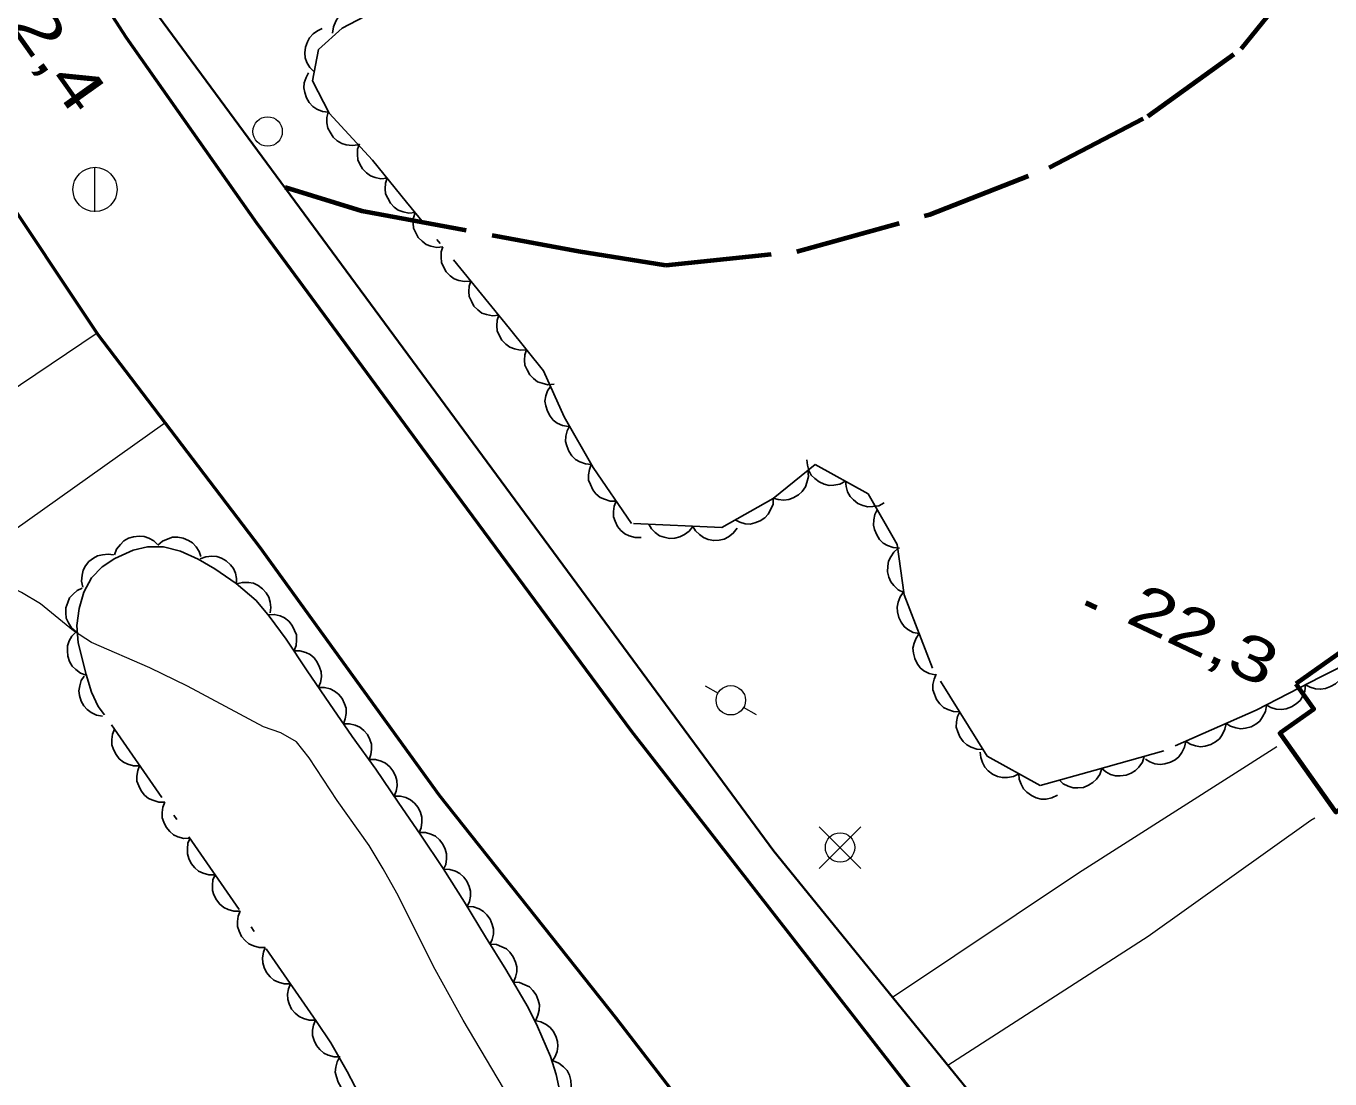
# Model space of a CAD drawing. Extents: x 356765 to 358572, y 5103174 to 5104650.
# Drawn here: x 357029.21 to 357073.46, y 5104052.73 to 5104088.48 of the extents above; entities that cross this region are included whole.
import ezdxf

# ---------------------------------------------------------------- set-up
doc = ezdxf.new("R2010")
doc.units = 0
doc.header["$LTSCALE"] = 0.6
doc.linetypes.add('DOT_DASHED', pattern=[7.7, 5, -1.2, 0.3, -1.2])
doc.linetypes.add('LONG_DASHED', pattern=[7.5, 6, -1.5])
for name, color, linetype, lineweight in [('19', 7, 'Continuous', 13), ('2', 7, 'Continuous', 13), ('21', 7, 'Continuous', 53), ('22', 7, 'Continuous', 35), ('3', 7, 'Continuous', 140), ('31', 7, 'Continuous', 70), ('36', 7, 'Continuous', 13), ('44', 7, 'Continuous', 25)]:
    doc.layers.add(name, color=color, linetype=linetype, lineweight=lineweight)

msp = doc.modelspace()

# ---------------------------------------------------------------- linework, layer by layer
at = {"layer": '19'}
msp.add_line((357022.12, 5104066.62), (357033.92, 5104075.01), dxfattribs=at)
for points in [[(357031.62, 5104078.05), (357020.19, 5104070.36), (357020.33, 5104069.93)], [(357071.66, 5104064.01), (357064.93, 5104059.72), (357058.62, 5104055.5)], [(357060.49, 5104053.2), (357067.3, 5104057.58), (357072.82, 5104061.51), (357072.95, 5104061.59)]]:
    msp.add_lwpolyline(points, dxfattribs=at)
at = {"layer": '2'}
msp.add_lwpolyline([(357047.18, 5104049.44), (357044.04, 5104054.73), (357043.09, 5104056.45), (357041.79, 5104059.04), (357041.33, 5104059.86), (357040.85, 5104060.65), (357039.76, 5104062.18), (357038.82, 5104063.63), (357038.38, 5104064.18), (357037.85, 5104064.48), (357037.26, 5104064.69), (357034.69, 5104066.07), (357033.41, 5104066.69), (357031.43, 5104067.55), (357030.82, 5104067.94), (357029.69, 5104068.86), (357029.05, 5104069.25), (357027.71, 5104069.88), (357027.14, 5104070.19)], dxfattribs=at)
at = {"layer": '21'}
for points in [[(357013.37, 5104117.93), (357021.55, 5104104.79), (357028.8, 5104093.99), (357032.6, 5104088.09), (357037.03, 5104081.8), (357042.63, 5104074.18), (357049.74, 5104064.55), (357059.41, 5104052.15)], [(357010.13, 5104111.16), (357012.95, 5104106.67), (357018.36, 5104098.18), (357024.48, 5104088.75), (357031.64, 5104078.01), (357037.13, 5104070.8), (357043.23, 5104062.36), (357049.22, 5104054.8), (357051.56, 5104051.78)]]:
    msp.add_lwpolyline(points, dxfattribs=at)
at = {"layer": '22'}
msp.add_lwpolyline([(357221.36, 5103864.57), (357203.17, 5103886.01), (357184.34, 5103907.9), (357170.96, 5103923.59), (357161.12, 5103935.05), (357158.11, 5103938.34), (357149.98, 5103947.63), (357129.46, 5103972.34), (357111.79, 5103992.65), (357092.35, 5104015.36), (357072.16, 5104038.84), (357054.59, 5104060.46), (357032.27, 5104090.76), (357019.29, 5104110.68), (357013.99, 5104119.24)], dxfattribs=at)
at = {"layer": '22', "linetype": 'LONG_DASHED', "lineweight": 70}
msp.add_lwpolyline([(357038, 5104083.01), (357040.6, 5104082.2), (357047.96, 5104080.84), (357050.92, 5104080.36), (357055.37, 5104080.82), (357059.88, 5104082.08), (357063.94, 5104083.67), (357067.28, 5104085.42), (357070.45, 5104087.71), (357072.96, 5104090.8)], dxfattribs=at)
at = {"layer": '3'}
msp.add_line((357065.18, 5104068.9), (357065.54, 5104068.73), dxfattribs=at)
at = {"layer": '31'}
msp.add_lwpolyline([(357072.31, 5104066.15), (357072.92, 5104065.29), (357071.76, 5104064.47), (357073.66, 5104061.79), (357074.66, 5104062.49), (357076.12, 5104060.42), (357081.38, 5104064.14), (357077.41, 5104069.75), (357072.31, 5104066.15)], close=True, dxfattribs=at)
at = {"layer": '36'}
for p, q in [((357031.54, 5104082.17), (357031.54, 5104083.67)), ((357052.26, 5104066.08), (357052.7, 5104065.83)), ((357054, 5104065.09), (357053.56, 5104065.34)), ((357057.54, 5104059.88), (357056.13, 5104061.29)), ((357056.13, 5104059.88), (357057.54, 5104061.29))]:
    msp.add_line(p, q, dxfattribs=at)
for centre, radius in [((357037.4038, 5104084.8971), 0.5), ((357031.5447, 5104082.9312), 0.75), ((357053.1261, 5104065.5865), 0.5), ((357056.8368, 5104060.5874), 0.5)]:
    msp.add_circle(centre, radius, dxfattribs=at)
at = {"layer": '44', "linetype": 'DOT_DASHED'}
for points in [[(357075.36, 5104067.5), (357073.16, 5104066.38), (357070.96, 5104065.25), (357067.83, 5104063.87), (357065.5, 5104063.21), (357063.63, 5104062.69), (357061.83, 5104063.69), (357059.97, 5104066.68), (357059.01, 5104069.17), (357058.78, 5104070.87), (357057.79, 5104072.59), (357055.99, 5104073.59), (357054.56, 5104072.44), (357052.82, 5104071.45), (357049.76, 5104071.59), (357048.46, 5104073.49), (357047.47, 5104075.21), (357046.77, 5104076.77), (357045.61, 5104078.21), (357042.12, 5104082.5), (357040.96, 5104083.93), (357039.49, 5104085.52), (357038.93, 5104086.62), (357039.13, 5104087.68), (357039.93, 5104088.41), (357044.09, 5104090.58)], [(357040.63, 5104051.99), (357040.11, 5104052.98), (357039.55, 5104053.95), (357039.06, 5104054.68), (357031.87, 5104065.09), (357031.65, 5104065.38), (357031.43, 5104065.86), (357031.24, 5104066.46), (357030.97, 5104067.54), (357030.93, 5104068.12), (357031.01, 5104068.7), (357031.17, 5104069.26), (357031.43, 5104069.74), (357031.79, 5104070.12), (357032.22, 5104070.4), (357032.84, 5104070.68), (357033.33, 5104070.8), (357033.87, 5104070.8), (357034.45, 5104070.65), (357035.05, 5104070.38), (357035.61, 5104070.05), (357036.34, 5104069.55), (357037.01, 5104068.97), (357037.46, 5104068.44), (357038.03, 5104067.66), (357038.75, 5104066.59), (357039.5, 5104065.48), (357040.28, 5104064.36), (357041.08, 5104063.25), (357041.84, 5104062.13), (357042.61, 5104061.01), (357043.36, 5104059.88), (357044.09, 5104058.73), (357044.8, 5104057.55), (357045.49, 5104056.44), (357046.25, 5104055.16), (357046.56, 5104054.51), (357047.01, 5104053.49), (357047.2, 5104052.88), (357047.36, 5104052.15)]]:
    msp.add_lwpolyline(points, dxfattribs=at)
at = {"layer": '44'}
for points in [[(357039.61, 5104088.24), (357039.64, 5104088.45), (357039.72, 5104088.64), (357039.8, 5104088.78), (357039.93, 5104088.9), (357040.09, 5104089), (357040.27, 5104089.06), (357040.43, 5104089.09), (357040.61, 5104089.07), (357040.78, 5104089.02), (357040.94, 5104088.94)], [(357038.99, 5104086.92), (357038.84, 5104087.07), (357038.74, 5104087.24), (357038.68, 5104087.4), (357038.67, 5104087.57), (357038.69, 5104087.76), (357038.76, 5104087.94), (357038.83, 5104088.08), (357038.95, 5104088.21), (357039.1, 5104088.32), (357039.26, 5104088.39)], [(357039.47, 5104085.55), (357039.27, 5104085.58), (357039.08, 5104085.66), (357038.94, 5104085.75), (357038.82, 5104085.88), (357038.72, 5104086.04), (357038.67, 5104086.22), (357038.63, 5104086.38), (357038.65, 5104086.55), (357038.71, 5104086.73), (357038.79, 5104086.89)], [(357040.48, 5104084.45), (357040.28, 5104084.42), (357040.07, 5104084.44), (357039.92, 5104084.49), (357039.77, 5104084.58), (357039.63, 5104084.71), (357039.53, 5104084.87), (357039.45, 5104085.01), (357039.42, 5104085.19), (357039.42, 5104085.37), (357039.46, 5104085.55)], [(357041.46, 5104083.31), (357041.25, 5104083.29), (357041.05, 5104083.34), (357040.9, 5104083.39), (357040.76, 5104083.49), (357040.63, 5104083.63), (357040.53, 5104083.79), (357040.47, 5104083.94), (357040.45, 5104084.12), (357040.46, 5104084.3), (357040.52, 5104084.48)], [(357042.41, 5104082.15), (357042.2, 5104082.13), (357042, 5104082.17), (357041.84, 5104082.23), (357041.7, 5104082.33), (357041.57, 5104082.46), (357041.48, 5104082.63), (357041.41, 5104082.78), (357041.4, 5104082.95), (357041.41, 5104083.14), (357041.46, 5104083.31)], [(357043.35, 5104080.98), (357043.15, 5104080.96), (357042.95, 5104081.01), (357042.79, 5104081.06), (357042.65, 5104081.17), (357042.52, 5104081.3), (357042.43, 5104081.46), (357042.36, 5104081.61), (357042.34, 5104081.79), (357042.36, 5104081.97), (357042.41, 5104082.15)], [(357044.3, 5104079.82), (357044.09, 5104079.8), (357043.89, 5104079.84), (357043.74, 5104079.9), (357043.6, 5104080), (357043.47, 5104080.13), (357043.37, 5104080.3), (357043.31, 5104080.45), (357043.29, 5104080.63), (357043.3, 5104080.81), (357043.35, 5104080.98)], [(357045.25, 5104078.66), (357045.04, 5104078.64), (357044.84, 5104078.68), (357044.68, 5104078.73), (357044.54, 5104078.84), (357044.41, 5104078.97), (357044.32, 5104079.14), (357044.25, 5104079.29), (357044.24, 5104079.46), (357044.25, 5104079.65), (357044.3, 5104079.82)], [(357046.19, 5104077.49), (357045.98, 5104077.47), (357045.78, 5104077.52), (357045.63, 5104077.57), (357045.49, 5104077.68), (357045.36, 5104077.81), (357045.26, 5104077.98), (357045.2, 5104078.13), (357045.18, 5104078.3), (357045.2, 5104078.49), (357045.25, 5104078.66)], [(357047.13, 5104076.32), (357046.92, 5104076.3), (357046.72, 5104076.35), (357046.57, 5104076.4), (357046.43, 5104076.51), (357046.3, 5104076.64), (357046.21, 5104076.81), (357046.14, 5104076.96), (357046.12, 5104077.13), (357046.14, 5104077.32), (357046.19, 5104077.49)], [(357047.62, 5104074.88), (357047.41, 5104074.91), (357047.23, 5104075), (357047.1, 5104075.1), (357046.99, 5104075.23), (357046.9, 5104075.4), (357046.85, 5104075.58), (357046.82, 5104075.74), (357046.85, 5104075.92), (357046.91, 5104076.09), (357047.01, 5104076.24)], [(357048.4, 5104073.59), (357048.19, 5104073.61), (357048, 5104073.68), (357047.86, 5104073.76), (357047.73, 5104073.89), (357047.63, 5104074.04), (357047.56, 5104074.22), (357047.52, 5104074.37), (357047.53, 5104074.55), (357047.57, 5104074.73), (357047.65, 5104074.89)], [(357049.24, 5104072.35), (357049.03, 5104072.35), (357048.84, 5104072.41), (357048.69, 5104072.47), (357048.55, 5104072.59), (357048.44, 5104072.73), (357048.36, 5104072.91), (357048.3, 5104073.06), (357048.3, 5104073.24), (357048.33, 5104073.42), (357048.39, 5104073.59)], [(357055.74, 5104073.39), (357055.76, 5104073.18), (357055.71, 5104072.98), (357055.66, 5104072.83), (357055.55, 5104072.68), (357055.42, 5104072.56), (357055.25, 5104072.46), (357055.1, 5104072.4), (357054.93, 5104072.38), (357054.74, 5104072.4), (357054.57, 5104072.45)], [(357057.02, 5104073.02), (357056.83, 5104072.92), (357056.63, 5104072.89), (357056.47, 5104072.88), (357056.3, 5104072.92), (357056.13, 5104073), (357055.98, 5104073.12), (357055.86, 5104073.23), (357055.78, 5104073.39), (357055.73, 5104073.57), (357055.71, 5104073.75)], [(357058.33, 5104072.29), (357058.15, 5104072.19), (357057.95, 5104072.16), (357057.78, 5104072.15), (357057.61, 5104072.2), (357057.44, 5104072.27), (357057.29, 5104072.39), (357057.18, 5104072.51), (357057.09, 5104072.66), (357057.04, 5104072.84), (357057.02, 5104073.02)], [(357050.09, 5104071.11), (357049.88, 5104071.11), (357049.68, 5104071.17), (357049.53, 5104071.24), (357049.4, 5104071.35), (357049.28, 5104071.49), (357049.2, 5104071.67), (357049.15, 5104071.82), (357049.15, 5104072), (357049.17, 5104072.18), (357049.24, 5104072.35)], [(357054.57, 5104072.45), (357054.56, 5104072.24), (357054.48, 5104072.05), (357054.4, 5104071.9), (357054.28, 5104071.78), (357054.12, 5104071.68), (357053.94, 5104071.61), (357053.79, 5104071.57), (357053.61, 5104071.58), (357053.43, 5104071.63), (357053.27, 5104071.71)], [(357058.85, 5104070.75), (357058.64, 5104070.77), (357058.45, 5104070.84), (357058.3, 5104070.92), (357058.18, 5104071.05), (357058.08, 5104071.2), (357058.01, 5104071.38), (357057.97, 5104071.53), (357057.98, 5104071.71), (357058.02, 5104071.89), (357058.1, 5104072.05)], [(357051.84, 5104071.49), (357051.71, 5104071.33), (357051.55, 5104071.21), (357051.4, 5104071.13), (357051.23, 5104071.09), (357051.05, 5104071.08), (357050.86, 5104071.12), (357050.71, 5104071.17), (357050.56, 5104071.28), (357050.43, 5104071.41), (357050.34, 5104071.56)], [(357053.34, 5104071.43), (357053.21, 5104071.26), (357053.05, 5104071.14), (357052.9, 5104071.06), (357052.73, 5104071.02), (357052.55, 5104071.01), (357052.36, 5104071.05), (357052.2, 5104071.11), (357052.06, 5104071.21), (357051.93, 5104071.34), (357051.84, 5104071.49)], [(357032.21, 5104070.53), (357032.28, 5104070.72), (357032.41, 5104070.88), (357032.52, 5104071), (357032.68, 5104071.09), (357032.85, 5104071.14), (357033.04, 5104071.16), (357033.21, 5104071.15), (357033.37, 5104071.09), (357033.54, 5104071), (357033.67, 5104070.88)], [(357033.68, 5104070.85), (357033.84, 5104070.99), (357034.03, 5104071.07), (357034.18, 5104071.12), (357034.36, 5104071.12), (357034.54, 5104071.09), (357034.72, 5104071.01), (357034.86, 5104070.93), (357034.98, 5104070.8), (357035.08, 5104070.64), (357035.14, 5104070.47)], [(357059, 5104069.25), (357058.81, 5104069.34), (357058.66, 5104069.48), (357058.56, 5104069.61), (357058.49, 5104069.77), (357058.45, 5104069.95), (357058.46, 5104070.14), (357058.48, 5104070.31), (357058.56, 5104070.46), (357058.66, 5104070.62), (357058.8, 5104070.74)], [(357031.13, 5104069.43), (357031.09, 5104069.63), (357031.11, 5104069.83), (357031.14, 5104070), (357031.22, 5104070.15), (357031.34, 5104070.3), (357031.49, 5104070.41), (357031.63, 5104070.49), (357031.8, 5104070.53), (357031.99, 5104070.55), (357032.17, 5104070.52)], [(357035.12, 5104070.39), (357035.31, 5104070.46), (357035.51, 5104070.48), (357035.68, 5104070.47), (357035.84, 5104070.41), (357036, 5104070.32), (357036.14, 5104070.19), (357036.25, 5104070.06), (357036.31, 5104069.9), (357036.35, 5104069.72), (357036.35, 5104069.54)], [(357036.35, 5104069.54), (357036.55, 5104069.59), (357036.76, 5104069.59), (357036.92, 5104069.56), (357037.08, 5104069.48), (357037.23, 5104069.37), (357037.35, 5104069.23), (357037.44, 5104069.09), (357037.49, 5104068.92), (357037.51, 5104068.74), (357037.49, 5104068.56)], [(357030.9, 5104067.91), (357030.75, 5104068.05), (357030.64, 5104068.22), (357030.57, 5104068.37), (357030.55, 5104068.55), (357030.56, 5104068.73), (357030.62, 5104068.91), (357030.68, 5104069.06), (357030.8, 5104069.19), (357030.94, 5104069.31), (357031.11, 5104069.39)], [(357059.52, 5104067.85), (357059.32, 5104067.89), (357059.14, 5104067.99), (357059.01, 5104068.09), (357058.91, 5104068.24), (357058.83, 5104068.4), (357058.79, 5104068.59), (357058.77, 5104068.75), (357058.81, 5104068.92), (357058.88, 5104069.1), (357058.98, 5104069.24)], [(357037.42, 5104068.49), (357037.63, 5104068.5), (357037.83, 5104068.45), (357037.98, 5104068.38), (357038.12, 5104068.27), (357038.24, 5104068.13), (357038.32, 5104067.96), (357038.38, 5104067.81), (357038.39, 5104067.63), (357038.37, 5104067.45), (357038.31, 5104067.28)], [(357031.25, 5104066.44), (357031.05, 5104066.51), (357030.89, 5104066.63), (357030.77, 5104066.75), (357030.68, 5104066.9), (357030.62, 5104067.08), (357030.61, 5104067.27), (357030.61, 5104067.43), (357030.67, 5104067.6), (357030.76, 5104067.76), (357030.88, 5104067.89)], [(357060.06, 5104066.45), (357059.86, 5104066.49), (357059.68, 5104066.59), (357059.55, 5104066.69), (357059.45, 5104066.84), (357059.37, 5104067), (357059.33, 5104067.19), (357059.31, 5104067.35), (357059.35, 5104067.53), (357059.42, 5104067.7), (357059.52, 5104067.85)], [(357038.29, 5104067.27), (357038.5, 5104067.27), (357038.7, 5104067.21), (357038.85, 5104067.14), (357038.98, 5104067.03), (357039.09, 5104066.88), (357039.17, 5104066.71), (357039.22, 5104066.55), (357039.23, 5104066.38), (357039.2, 5104066.19), (357039.13, 5104066.03)], [(357073.97, 5104066.79), (357073.95, 5104066.59), (357073.87, 5104066.4), (357073.78, 5104066.26), (357073.65, 5104066.14), (357073.49, 5104066.05), (357073.31, 5104065.99), (357073.15, 5104065.96), (357072.97, 5104065.98), (357072.8, 5104066.03), (357072.64, 5104066.11)], [(357031.8, 5104065.05), (357031.6, 5104065.08), (357031.41, 5104065.17), (357031.28, 5104065.27), (357031.16, 5104065.4), (357031.07, 5104065.56), (357031.02, 5104065.75), (357031, 5104065.91), (357031.03, 5104066.08), (357031.08, 5104066.26), (357031.18, 5104066.41)], [(357060.9, 5104065.19), (357060.69, 5104065.2), (357060.49, 5104065.27), (357060.35, 5104065.34), (357060.22, 5104065.46), (357060.11, 5104065.61), (357060.04, 5104065.79), (357059.99, 5104065.94), (357059.99, 5104066.12), (357060.03, 5104066.3), (357060.1, 5104066.47)], [(357039.12, 5104066.02), (357039.33, 5104066.02), (357039.53, 5104065.97), (357039.68, 5104065.9), (357039.81, 5104065.79), (357039.93, 5104065.65), (357040.01, 5104065.47), (357040.07, 5104065.32), (357040.07, 5104065.14), (357040.04, 5104064.96), (357039.98, 5104064.79)], [(357072.64, 5104066.11), (357072.61, 5104065.9), (357072.53, 5104065.72), (357072.45, 5104065.58), (357072.32, 5104065.46), (357072.16, 5104065.36), (357071.98, 5104065.3), (357071.82, 5104065.27), (357071.64, 5104065.29), (357071.46, 5104065.34), (357071.3, 5104065.43)], [(357061.69, 5104063.92), (357061.48, 5104063.93), (357061.29, 5104063.99), (357061.14, 5104064.07), (357061.01, 5104064.19), (357060.9, 5104064.34), (357060.83, 5104064.51), (357060.78, 5104064.67), (357060.79, 5104064.85), (357060.82, 5104065.03), (357060.9, 5104065.19)], [(357071.31, 5104065.41), (357071.28, 5104065.2), (357071.18, 5104065.02), (357071.09, 5104064.88), (357070.95, 5104064.77), (357070.79, 5104064.69), (357070.6, 5104064.64), (357070.44, 5104064.62), (357070.27, 5104064.65), (357070.09, 5104064.71), (357069.94, 5104064.8)], [(357033.06, 5104063.36), (357032.85, 5104063.36), (357032.66, 5104063.42), (357032.51, 5104063.49), (357032.37, 5104063.6), (357032.26, 5104063.74), (357032.17, 5104063.92), (357032.12, 5104064.07), (357032.12, 5104064.25), (357032.14, 5104064.43), (357032.21, 5104064.6)], [(357039.97, 5104064.79), (357040.18, 5104064.79), (357040.38, 5104064.74), (357040.53, 5104064.67), (357040.67, 5104064.56), (357040.79, 5104064.42), (357040.87, 5104064.25), (357040.93, 5104064.1), (357040.93, 5104063.92), (357040.91, 5104063.74), (357040.85, 5104063.57)], [(357069.94, 5104064.8), (357069.9, 5104064.6), (357069.81, 5104064.41), (357069.72, 5104064.28), (357069.58, 5104064.17), (357069.42, 5104064.08), (357069.23, 5104064.03), (357069.07, 5104064.01), (357068.9, 5104064.04), (357068.72, 5104064.1), (357068.57, 5104064.2)], [(357068.57, 5104064.2), (357068.53, 5104063.99), (357068.44, 5104063.81), (357068.34, 5104063.67), (357068.21, 5104063.56), (357068.05, 5104063.48), (357067.86, 5104063.43), (357067.7, 5104063.41), (357067.52, 5104063.43), (357067.35, 5104063.5), (357067.2, 5104063.59)], [(357062.91, 5104063.09), (357062.72, 5104063), (357062.52, 5104062.96), (357062.35, 5104062.96), (357062.18, 5104063), (357062.01, 5104063.08), (357061.86, 5104063.19), (357061.75, 5104063.31), (357061.67, 5104063.47), (357061.61, 5104063.64), (357061.59, 5104063.82)], [(357067.16, 5104063.68), (357067.1, 5104063.48), (357066.98, 5104063.32), (357066.87, 5104063.2), (357066.72, 5104063.11), (357066.55, 5104063.04), (357066.35, 5104063.02), (357066.19, 5104063.02), (357066.02, 5104063.07), (357065.86, 5104063.16), (357065.72, 5104063.27)], [(357033.91, 5104062.13), (357033.71, 5104062.13), (357033.51, 5104062.19), (357033.36, 5104062.25), (357033.23, 5104062.37), (357033.11, 5104062.51), (357033.03, 5104062.68), (357032.97, 5104062.84), (357032.97, 5104063.01), (357033, 5104063.2), (357033.06, 5104063.36)], [(357040.86, 5104063.58), (357041.07, 5104063.58), (357041.26, 5104063.52), (357041.41, 5104063.45), (357041.55, 5104063.33), (357041.66, 5104063.19), (357041.74, 5104063.02), (357041.79, 5104062.86), (357041.8, 5104062.68), (357041.77, 5104062.5), (357041.7, 5104062.33)], [(357065.72, 5104063.27), (357065.66, 5104063.07), (357065.54, 5104062.91), (357065.42, 5104062.79), (357065.27, 5104062.7), (357065.1, 5104062.63), (357064.91, 5104062.61), (357064.75, 5104062.61), (357064.58, 5104062.67), (357064.41, 5104062.75), (357064.28, 5104062.87)], [(357064.22, 5104062.36), (357064.03, 5104062.27), (357063.83, 5104062.23), (357063.66, 5104062.23), (357063.49, 5104062.27), (357063.33, 5104062.35), (357063.18, 5104062.47), (357063.06, 5104062.58), (357062.98, 5104062.74), (357062.92, 5104062.91), (357062.91, 5104063.09)], [(357041.7, 5104062.33), (357041.91, 5104062.33), (357042.1, 5104062.28), (357042.25, 5104062.21), (357042.39, 5104062.09), (357042.51, 5104061.95), (357042.59, 5104061.78), (357042.64, 5104061.62), (357042.64, 5104061.45), (357042.62, 5104061.26), (357042.55, 5104061.1)], [(357034.77, 5104060.9), (357034.56, 5104060.89), (357034.36, 5104060.95), (357034.21, 5104061.02), (357034.08, 5104061.13), (357033.96, 5104061.28), (357033.88, 5104061.45), (357033.83, 5104061.6), (357033.82, 5104061.78), (357033.85, 5104061.96), (357033.91, 5104062.13)], [(357042.55, 5104061.1), (357042.76, 5104061.1), (357042.95, 5104061.04), (357043.1, 5104060.97), (357043.24, 5104060.85), (357043.35, 5104060.7), (357043.43, 5104060.53), (357043.48, 5104060.37), (357043.48, 5104060.2), (357043.45, 5104060.01), (357043.38, 5104059.85)], [(357035.62, 5104059.66), (357035.41, 5104059.66), (357035.22, 5104059.72), (357035.06, 5104059.78), (357034.93, 5104059.9), (357034.81, 5104060.04), (357034.73, 5104060.21), (357034.68, 5104060.37), (357034.68, 5104060.54), (357034.7, 5104060.73), (357034.77, 5104060.9)], [(357036.47, 5104058.43), (357036.26, 5104058.43), (357036.07, 5104058.48), (357035.92, 5104058.55), (357035.78, 5104058.66), (357035.67, 5104058.81), (357035.58, 5104058.98), (357035.53, 5104059.13), (357035.53, 5104059.31), (357035.55, 5104059.49), (357035.62, 5104059.66)], [(357043.38, 5104059.85), (357043.59, 5104059.84), (357043.78, 5104059.78), (357043.93, 5104059.7), (357044.06, 5104059.58), (357044.17, 5104059.44), (357044.25, 5104059.26), (357044.29, 5104059.1), (357044.29, 5104058.93), (357044.26, 5104058.75), (357044.18, 5104058.58)], [(357037.32, 5104057.19), (357037.12, 5104057.19), (357036.92, 5104057.25), (357036.77, 5104057.32), (357036.64, 5104057.43), (357036.52, 5104057.57), (357036.44, 5104057.75), (357036.38, 5104057.9), (357036.38, 5104058.08), (357036.41, 5104058.26), (357036.47, 5104058.43)], [(357044.18, 5104058.58), (357044.39, 5104058.57), (357044.58, 5104058.5), (357044.73, 5104058.42), (357044.85, 5104058.3), (357044.96, 5104058.15), (357045.03, 5104057.97), (357045.07, 5104057.81), (357045.07, 5104057.64), (357045.03, 5104057.46), (357044.95, 5104057.29)], [(357038.18, 5104055.96), (357037.97, 5104055.96), (357037.77, 5104056.01), (357037.62, 5104056.08), (357037.49, 5104056.2), (357037.37, 5104056.34), (357037.29, 5104056.51), (357037.24, 5104056.67), (357037.23, 5104056.84), (357037.26, 5104057.03), (357037.32, 5104057.19)], [(357044.96, 5104057.3), (357045.17, 5104057.29), (357045.36, 5104057.22), (357045.51, 5104057.15), (357045.63, 5104057.03), (357045.74, 5104056.88), (357045.82, 5104056.7), (357045.86, 5104056.54), (357045.86, 5104056.37), (357045.82, 5104056.19), (357045.75, 5104056.02)], [(357039.03, 5104054.73), (357038.82, 5104054.72), (357038.62, 5104054.78), (357038.47, 5104054.85), (357038.34, 5104054.96), (357038.22, 5104055.1), (357038.14, 5104055.28), (357038.09, 5104055.43), (357038.08, 5104055.61), (357038.11, 5104055.79), (357038.18, 5104055.96)], [(357045.74, 5104056.02), (357045.95, 5104056), (357046.14, 5104055.93), (357046.29, 5104055.86), (357046.41, 5104055.73), (357046.52, 5104055.58), (357046.59, 5104055.4), (357046.63, 5104055.25), (357046.62, 5104055.07), (357046.58, 5104054.89), (357046.51, 5104054.73)], [(357039.87, 5104053.48), (357039.66, 5104053.48), (357039.46, 5104053.54), (357039.31, 5104053.61), (357039.18, 5104053.73), (357039.06, 5104053.87), (357038.99, 5104054.04), (357038.93, 5104054.2), (357038.93, 5104054.38), (357038.96, 5104054.56), (357039.03, 5104054.73)], [(357046.47, 5104054.71), (357046.68, 5104054.67), (357046.86, 5104054.58), (357046.99, 5104054.48), (357047.1, 5104054.35), (357047.19, 5104054.18), (357047.24, 5104054), (357047.26, 5104053.84), (357047.23, 5104053.66), (357047.17, 5104053.49), (357047.08, 5104053.34)], [(357040.55, 5104052.14), (357040.34, 5104052.17), (357040.16, 5104052.25), (357040.01, 5104052.33), (357039.89, 5104052.46), (357039.8, 5104052.62), (357039.74, 5104052.8), (357039.7, 5104052.96), (357039.72, 5104053.13), (357039.77, 5104053.31), (357039.85, 5104053.47)], [(357047.1, 5104053.34), (357047.29, 5104053.26), (357047.45, 5104053.14), (357047.57, 5104053.02), (357047.65, 5104052.86), (357047.7, 5104052.68), (357047.71, 5104052.49), (357047.7, 5104052.33), (357047.64, 5104052.16), (357047.54, 5104052.01), (357047.42, 5104051.87)]]:
    msp.add_lwpolyline(points, dxfattribs=at)

# ---------------------------------------------------------------- texts
at = {"layer": '3'}
for s, rotation, width, p in [('22,4   ', 305.404, 1.4, (357027.65, 5104089.84)), ('22,3   ', 334.619, 1.35, (357066.48, 5104068.26))]:
    msp.add_text(s, height=1.5, rotation=rotation, dxfattribs=dict(at, width=width)).set_placement(p)

doc.saveas('drawing.dxf')
